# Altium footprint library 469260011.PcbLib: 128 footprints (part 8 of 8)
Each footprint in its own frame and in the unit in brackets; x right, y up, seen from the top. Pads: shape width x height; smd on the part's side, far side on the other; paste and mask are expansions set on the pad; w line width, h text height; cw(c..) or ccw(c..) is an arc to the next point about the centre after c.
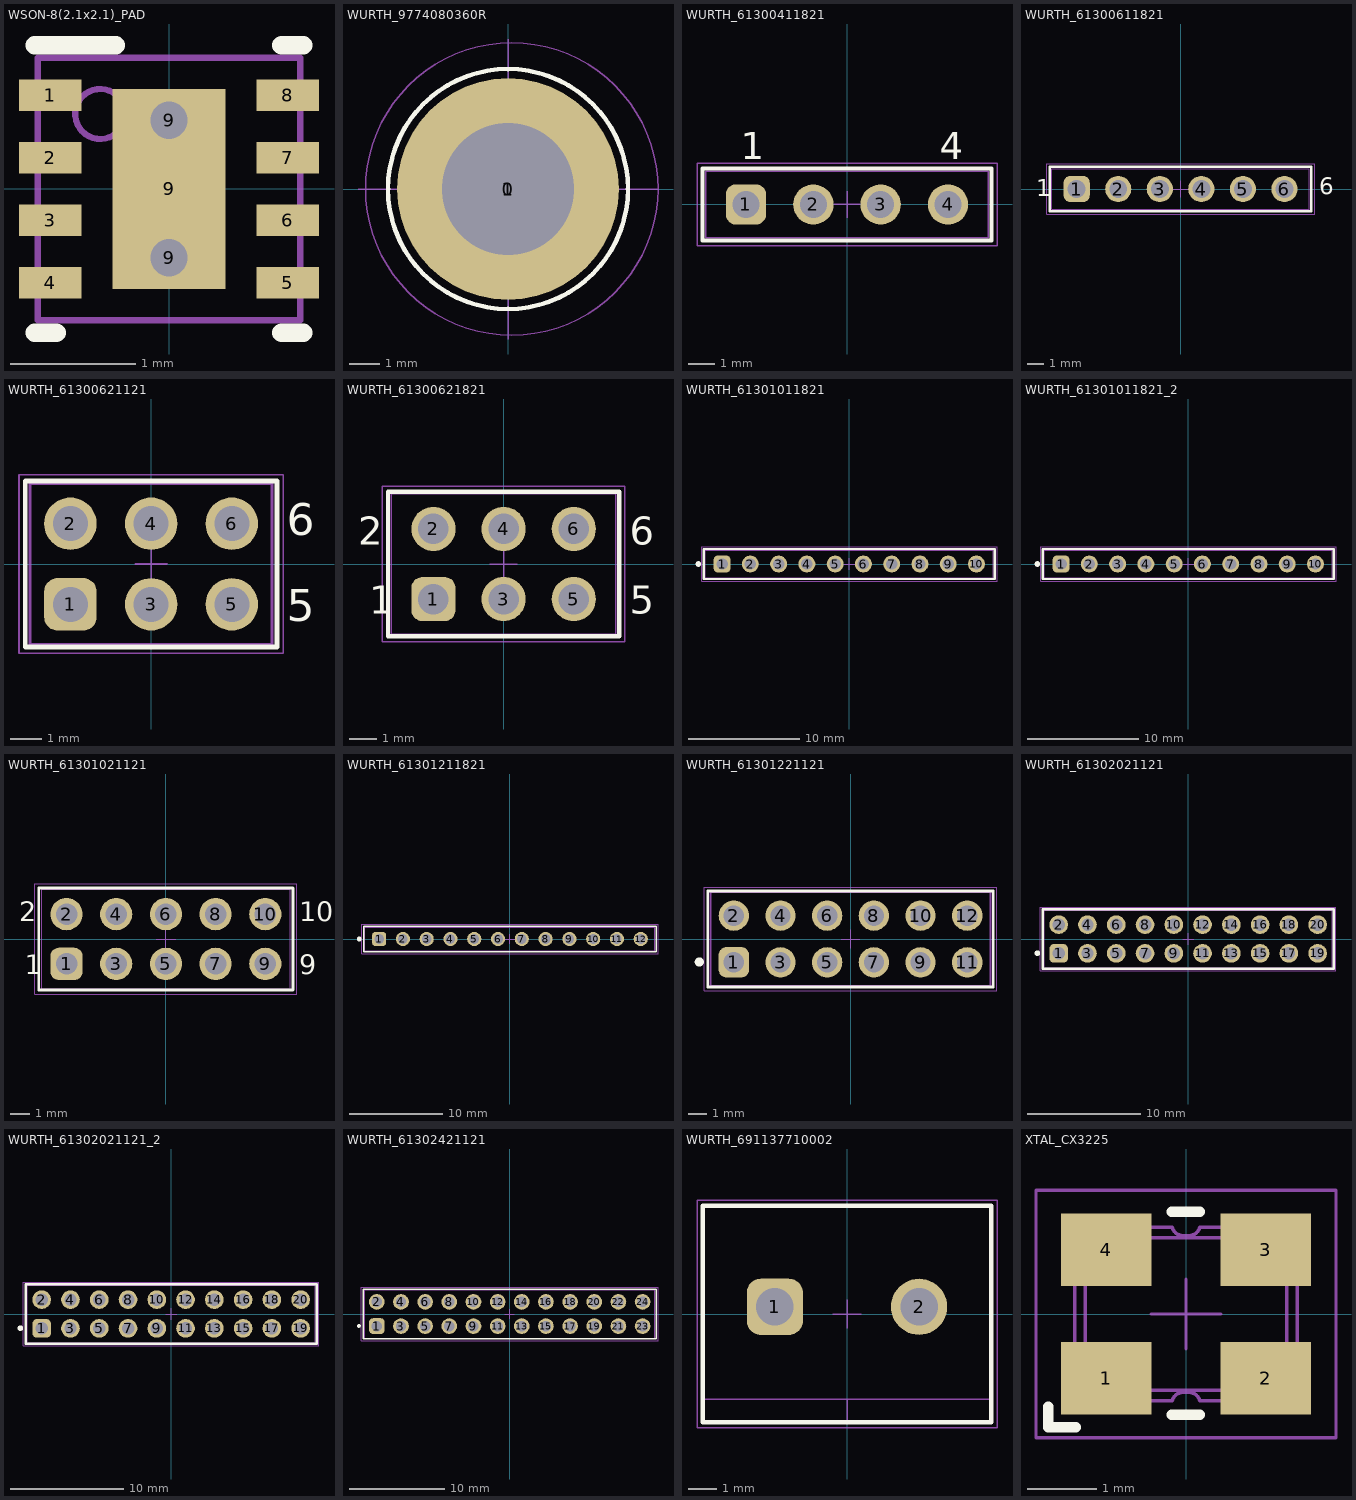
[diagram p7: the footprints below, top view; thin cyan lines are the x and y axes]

## WSON-8(2.1x2.1)_PAD [mm] "8-WFDFN Exposed Pad, 8-WSON (2x2), DSG0008A_TEX"
height 0.8
pads (11):
  rect 0.5x0.25 smd paste+0 mask+0: 1(-0.95,0.75) 2(-0.95,0.25) 3(-0.95,-0.25) 4(-0.95,-0.75) 5(0.95,-0.75) 6(0.95,-0.25) 7(0.95,0.25) 8(0.95,0.75)
  round 0.5 hole 0.3 paste+0 mask+0.076: 9(0,-0.55) 9(0,0.55)
  rect 0.9x1.6 smd paste-0.45 mask+0: 9(0,0)
Top Overlay:
  lines w0.15: -1.075,-1.15 -0.9,-1.15 ; -1.075,1.15 -0.425,1.15 ; 0.9,-1.15 1.075,-1.15 ; 0.9,1.15 1.075,1.15
Top Paste:
  region: -0.449,-0.761 -0.45,-0.751 -0.45,-0.149 -0.449,-0.139 -0.446,-0.13 -0.442,-0.122 -0.436,-0.114 -0.428,-0.108 -0.42,-0.104 -0.411,-0.101 -0.401,-0.1 0.401,-0.1 0.411,-0.101 0.42,-0.104 0.428,-0.108 0.436,-0.114 0.442,-0.122 0.446,-0.13 0.449,-0.139 0.45,-0.149 0.45,-0.751 0.449,-0.761 0.446,-0.77 0.442,-0.778 0.436,-0.786 0.428,-0.792 0.42,-0.796 0.411,-0.799 0.401,-0.8 -0.401,-0.8 -0.411,-0.799 -0.42,-0.796 -0.428,-0.792 -0.436,-0.786 -0.442,-0.778 -0.446,-0.77
  region: -0.449,0.139 -0.45,0.149 -0.45,0.751 -0.449,0.761 -0.446,0.77 -0.442,0.778 -0.436,0.786 -0.428,0.792 -0.42,0.796 -0.411,0.799 -0.401,0.8 0.401,0.8 0.411,0.799 0.42,0.796 0.428,0.792 0.436,0.786 0.442,0.778 0.446,0.77 0.449,0.761 0.45,0.751 0.45,0.149 0.449,0.139 0.446,0.13 0.442,0.122 0.436,0.114 0.428,0.108 0.42,0.104 0.411,0.101 0.401,0.1 -0.401,0.1 -0.411,0.101 -0.42,0.104 -0.428,0.108 -0.436,0.114 -0.442,0.122 -0.446,0.13
Top Assembly:
  circle w0.05: c-0.55,0.6 r0.2
  lines w0.05: -1.05,-1.05 1.05,-1.05 1.05,1.05 -1.05,1.05 -1.05,-1.05
3D body "DSG0008A.stp": height 0.77, standoff 0, extent -1,-1 1,1

## WURTH_9774080360R [mm]
pads (2):
  round 2.2 hole 4.4 unplated: 0(0,0)
  round 7.4 smd paste-10: 1(0,0)
Top Overlay:
  circle w0.15: c0,0 r4
Top Paste:
  lines w1.4: -2.767,-1.083 ccw(c0,0) -1.202,-2.718 ; -2.718,1.202 cw(c0,0) -1.083,2.767 ; 1.083,-2.767 ccw(c0,0) 2.718,-1.202 ; 1.202,2.718 cw(c0,0) 2.767,1.083
Mechanical 1:
  lines w0.05: -5,0 5,0 ; 0,-5 0,5
Top Assembly:
  circle w0.05: c0,0 r4
  text ".Designator" at -2.252,-0.226 h1
Top Courtyard:
  circle w0.05: c0.125,0 r4.875
  lines w0.05: -0.5,0 0.5,0 ; 0,-0.5 0,0.5
3D body "Download_STP_9774080360R_rev1.stp": height 9.4, standoff 0, extent -2.918,-2.934 3.076,3.053

## WURTH_61300411821 [mm] "Socket Header, Pitch 2.54 mm, THT, Vertical, single row, 4p"
height 8.5
pads (4):
  rrect50% 1.52x1.52 hole 1.02: 1(-3.81,0)
  round 1.52 hole 1.02: 2(-1.27,0) 3(1.27,0) 4(3.81,0)
Top Overlay:
  lines w0.15: -5.455,-1.35 -5.455,1.35 5.455,1.35 5.455,-1.35 -5.455,-1.35
  text "1" at -4,1.7 h1.02
  text "4" at 3.5,1.7 h1.02
Top Assembly:
  lines w0.05: -5.33,-1.25 5.33,-1.25 5.33,1.25 -5.33,1.25 -5.33,-1.25
  text ".Designator" at -2.252,-0.226 h1
Top Courtyard:
  lines w0.05: -0.5,0 0.5,0 ; 0,-0.5 0,0.5 ; -5.655,-1.55 -5.655,1.55 5.655,1.55 5.655,-1.55 -5.655,-1.55
3D body "61300411821.stp": height 8.55, standoff -3.05, extent -5.33,-1.25 5.33,1.25

## WURTH_61300611821 [mm] "Socket Header, Pitch 2.54 mm, THT, Vertical, single row, 6p"
height 8.5
pads (6):
  rrect50% 1.6x1.6 hole 1.1: 1(-6.35,0)
  round 1.6 hole 1.1: 2(-3.81,0) 3(-1.27,0) 4(1.27,0) 5(3.81,0) 6(6.35,0)
Top Overlay:
  lines w0.15: -7.995,-1.35 -7.995,1.35 7.995,1.35 7.995,-1.35 -7.995,-1.35
  text "1" at -8.84,-0.45 h1.02
  text "6" at 8.49,-0.35 h1.02
Top Assembly:
  lines w0.05: -7.87,-1.25 7.87,-1.25 7.87,1.25 -7.87,1.25 -7.87,-1.25
  text ".Designator" at -2.252,-0.226 h1
Top Courtyard:
  lines w0.05: -0.5,0 0.5,0 ; 0,-0.5 0,0.5 ; -8.195,-1.55 -8.195,1.55 8.195,1.55 8.195,-1.55 -8.195,-1.55
3D body "61300611821.stp": height 8.55, standoff -3.06, extent -7.87,-1.25 7.87,1.25

## WURTH_61300621121 [mm] "Pin Header, pitch 2.54 mm, THT, Vertical, dual row, 6p"
height 8.54
pads (6):
  rrect50% 1.65x1.65 hole 1.1: 1(-2.54,-1.27)
  round 1.65 hole 1.1: 2(-2.54,1.27) 3(0,-1.27) 4(0,1.27) 5(2.54,-1.27) 6(2.54,1.27)
Top Overlay:
  lines w0.15: -3.96,-2.615 3.96,-2.615 3.96,2.615 -3.96,2.615 -3.96,-2.615
  text "5" at 4.27,-1.8 h1.02
  text "6" at 4.27,0.9 h1.02
Top Assembly:
  lines w0.1: -3.81,-2.54 3.81,-2.54 3.81,2.54 -3.81,2.54 -3.81,-2.54
  text ".Designator" at -2.252,-0.226 h1
Top Courtyard:
  lines w0.05: -0.5,0 0.5,0 ; 0,-0.5 0,0.5 ; -4.16,-2.815 -4.16,2.815 4.16,2.815 4.16,-2.815 -4.16,-2.815
3D body "61300621121.stp": height 8.59, standoff -2.95, extent -3.81,-2.54 3.81,2.54

## WURTH_61300621821 [mm] "Socket Header, Pitch 2.54 mm, THT, Vertical, dual row, 6p"
height 8.4
pads (6):
  rrect50% 1.6x1.6 hole 1.1: 1(-2.54,-1.27)
  round 1.6 hole 1.1: 2(-2.54,1.27) 3(0,-1.27) 4(0,1.27) 5(2.54,-1.27) 6(2.54,1.27)
Top Overlay:
  lines w0.15: -4.185,-2.615 -4.185,2.615 4.185,2.615 4.185,-2.615 -4.185,-2.615
  text "5" at 4.57,-1.8 h1.02
  text "6" at 4.57,0.7 h1.02
  text "2" at -5.27,0.7 h1.02
  text "1" at -4.87,-1.8 h1.02
Top Assembly:
  lines w0.05: -4.06,-2.54 4.06,-2.54 4.06,2.54 -4.06,2.54 -4.06,-2.54
  text ".Designator" at -2.252,-0.226 h1
Top Courtyard:
  lines w0.05: -0.5,0 0.5,0 ; 0,-0.5 0,0.5 ; -4.385,-2.815 4.385,-2.815 4.385,2.815 -4.385,2.815 -4.385,-2.815
3D body "61300621821.stp": height 8.45, standoff -3.05, extent -4.06,-2.54 4.06,2.54

## WURTH_61301011821 [mm] "Socket Header, Pitch 2.54 mm, THT, Vertical, single row, 10p"
height 8.5
pads (10):
  rrect50% 1.52x1.52 hole 1.02: 1(-11.43,0)
  round 1.52 hole 1.02: 2(-8.89,0) 3(-6.35,0) 4(-3.81,0) 5(-1.27,0) 6(1.27,0) 7(3.81,0) 8(6.35,0) 9(8.89,0) 10(11.43,0)
Top Overlay:
  circle w0.25: c-13.56,0 r0.125
  lines w0.2: -13.075,-1.35 13.075,-1.35 13.075,1.35 -13.075,1.35 -13.075,-1.35
Top Assembly:
  lines w0.1: -12.95,-1.25 12.95,-1.25 12.95,1.25 -12.95,1.25 -12.95,-1.25
  text ".Designator" at -2.252,-0.226 h1
Top Courtyard:
  lines w0.05: -0.5,0 0.5,0 ; 0,-0.5 0,0.5 ; -13.275,-1.55 13.275,-1.55 13.275,1.55 -13.275,1.55 -13.275,-1.55
3D body "61301011821.stp": height 8.55, standoff -3.06, extent -12.95,-1.25 12.95,1.25

## WURTH_61301011821_2 [mm]
pads (10):
  rrect50% 1.52x1.52 hole 1.02: 1(-11.43,0)
  round 1.52 hole 1.02: 2(-8.89,0) 3(-6.35,0) 4(-3.81,0) 5(-1.27,0) 6(1.27,0) 7(3.81,0) 8(6.35,0) 9(8.89,0) 10(11.43,0)
Top Overlay:
  circle w0.25: c-13.56,0 r0.125
  lines w0.2: -13.075,-1.35 -13.075,1.35 13.075,1.35 13.075,-1.35 -13.075,-1.35
Top Assembly:
  lines w0.1: -12.95,-1.25 -12.95,1.25 12.95,1.25 12.95,-1.25 -12.95,-1.25
  text ".Designator" at -2.252,-0.226 h1
Top Courtyard:
  lines w0.05: -0.5,0 0.5,0 ; 0,-0.5 0,0.5 ; -13.275,-1.55 -13.275,1.55 13.275,1.55 13.275,-1.55 -13.275,-1.55
3D body "61301011821.stp": height 8.55, standoff -3.06, extent -12.95,-1.25 12.95,1.25

## WURTH_61301021121 [mm] "Pin Header, pitch 2.54 mm, THT, Vertical, dual row, 10p"
height 8.54
pads (10):
  rrect50% 1.65x1.65 hole 1.1: 1(-5.08,-1.27)
  round 1.65 hole 1.1: 2(-5.08,1.27) 3(-2.54,-1.27) 4(-2.54,1.27) 5(0,-1.27) 6(0,1.27) 7(2.54,-1.27) 8(2.54,1.27) 9(5.08,-1.27) 10(5.08,1.27)
Top Overlay:
  lines w0.15: -6.5,-2.615 -6.5,2.615 6.5,2.615 6.5,-2.615 -6.5,-2.615
  text "10" at 6.81,0.9 h1.02
  text "9" at 6.81,-1.8 h1.02
  text "1" at -7.21,-1.8 h1.02
  text "2" at -7.51,0.9 h1.02
Top Assembly:
  lines w0.05: -6.35,-2.54 -6.35,2.54 6.35,2.54 6.35,-2.54 -6.35,-2.54
  text ".Designator" at -2.252,-0.226 h1
Top Courtyard:
  lines w0.05: -0.5,0 0.5,0 ; 0,-0.5 0,0.5 ; -6.7,-2.815 6.7,-2.815 6.7,2.815 -6.7,2.815 -6.7,-2.815
3D body "61301021121.stp": height 8.59, standoff -2.95, extent -6.35,-2.54 6.35,2.54

## WURTH_61301211821 [mm] "Socket Header, Pitch 2.54 mm, THT, Vertical, single row, 12p"
height 8.5
pads (12):
  rrect50% 1.52x1.52 hole 1.02: 1(-13.97,0)
  round 1.52 hole 1.02: 2(-11.43,0) 3(-8.89,0) 4(-6.35,0) 5(-3.81,0) 6(-1.27,0) 7(1.27,0) 8(3.81,0) 9(6.35,0) 10(8.89,0) 11(11.43,0) 12(13.97,0)
Top Overlay:
  circle w0.25: c-16.1,0 r0.125
  lines w0.15: -15.615,-1.35 -15.615,1.35 15.615,1.35 15.615,-1.35 -15.615,-1.35
Top Assembly:
  lines w0.05: -15.49,-1.25 -15.49,1.25 15.49,1.25 15.49,-1.25 -15.49,-1.25
  text ".Designator" at -2.252,-0.226 h1
Top Courtyard:
  lines w0.05: -0.5,0 0.5,0 ; 0,-0.5 0,0.5 ; -15.815,-1.55 -15.815,1.55 15.815,1.55 15.815,-1.55 -15.815,-1.55
3D body "61301211821.stp": height 8.55, standoff -3.06, extent -15.49,-1.25 15.49,1.25

## WURTH_61301221121 [mm] "Pin Header, pitch 2.54 mm, THT, Vertical, dual row, 12p"
height 8.54
pads (12):
  rrect50% 1.65x1.65 hole 1.1: 1(-6.35,-1.27)
  round 1.65 hole 1.1: 2(-6.35,1.27) 3(-3.81,-1.27) 4(-3.81,1.27) 5(-1.27,-1.27) 6(-1.27,1.27) 7(1.27,-1.27) 8(1.27,1.27) 9(3.81,-1.27) 10(3.81,1.27) 11(6.35,-1.27) 12(6.35,1.27)
Top Overlay:
  circle w0.25: c-8.23,-1.25 r0.125
  lines w0.15: -7.77,-2.615 7.77,-2.615 7.77,2.615 -7.77,2.615 -7.77,-2.615
Top Assembly:
  lines w0.1: -7.62,-2.54 7.62,-2.54 7.62,2.54 -7.62,2.54 -7.62,-2.54
  text ".Designator" at -3.378,-0.339 h1.5
Top Courtyard:
  lines w0.05: -0.5,0 0.5,0 ; 0,-0.5 0,0.5 ; -7.97,-2.815 -7.97,2.815 7.97,2.815 7.97,-2.815 -7.97,-2.815
3D body "61301221121.stp": height 8.59, standoff -2.95, extent -7.62,-2.54 7.62,2.54

## WURTH_61302021121 [mm] "Pin Header, pitch 2.54 mm, THT, Vertical, dual row, 20p"
height 8.54
pads (20):
  rrect50% 1.65x1.65 hole 1.1: 1(-11.43,-1.27)
  round 1.65 hole 1.1: 2(-11.43,1.27) 3(-8.89,-1.27) 4(-8.89,1.27) 5(-6.35,-1.27) 6(-6.35,1.27) 7(-3.81,-1.27) 8(-3.81,1.27) 9(-1.27,-1.27) 10(-1.27,1.27) 11(1.27,-1.27) 12(1.27,1.27) 13(3.81,-1.27) 14(3.81,1.27) 15(6.35,-1.27) 16(6.35,1.27) 17(8.89,-1.27) 18(8.89,1.27) 19(11.43,-1.27) 20(11.43,1.27)
Top Overlay:
  circle w0.25: c-13.31,-1.25 r0.125
  lines w0.2: -12.85,-2.615 12.85,-2.615 12.85,2.615 -12.85,2.615 -12.85,-2.615
Top Assembly:
  circle w0.05: c-11.43,-1.27 r0.5
  lines w0.1: -12.7,-2.54 12.7,-2.54 12.7,2.54 -12.7,2.54 -12.7,-2.54
  text ".Designator" at -2.252,-0.226 h1
Top Courtyard:
  lines w0.05: -0.5,0 0.5,0 ; 0,-0.5 0,0.5 ; -13.05,-2.815 13.05,-2.815 13.05,2.815 -13.05,2.815 -13.05,-2.815
3D body "61302021121.stp": height 8.59, standoff -2.95, extent -12.7,-2.54 12.7,2.54

## WURTH_61302021121_2 [mm]
pads (20):
  rrect50% 1.65x1.65 hole 1.1: 1(-11.43,-1.27)
  round 1.65 hole 1.1: 2(-11.43,1.27) 3(-8.89,-1.27) 4(-8.89,1.27) 5(-6.35,-1.27) 6(-6.35,1.27) 7(-3.81,-1.27) 8(-3.81,1.27) 9(-1.27,-1.27) 10(-1.27,1.27) 11(1.27,-1.27) 12(1.27,1.27) 13(3.81,-1.27) 14(3.81,1.27) 15(6.35,-1.27) 16(6.35,1.27) 17(8.89,-1.27) 18(8.89,1.27) 19(11.43,-1.27) 20(11.43,1.27)
Top Overlay:
  circle w0.25: c-13.31,-1.25 r0.125
  lines w0.2: -12.85,-2.615 -12.85,2.615 12.85,2.615 12.85,-2.615 -12.85,-2.615
Top Assembly:
  circle w0.05: c-11.43,-1.27 r0.5
  lines w0.1: -12.7,-2.54 12.7,-2.54 12.7,2.54 -12.7,2.54 -12.7,-2.54
  text ".Designator" at -2.252,-0.226 h1
Top Courtyard:
  lines w0.05: -0.5,0 0.5,0 ; 0,-0.5 0,0.5 ; -13.05,-2.815 13.05,-2.815 13.05,2.815 -13.05,2.815 -13.05,-2.815
3D body "61302021121.stp": height 8.59, standoff -2.95, extent -12.7,-2.54 12.7,2.54

## WURTH_61302421121 [mm] "Pin Header, pitch 2.54 mm, THT, Vertical, dual row, 24p"
height 8.54
pads (24):
  rrect50% 1.65x1.65 hole 1.1: 1(-13.97,-1.27)
  round 1.65 hole 1.1: 2(-13.97,1.27) 3(-11.43,-1.27) 4(-11.43,1.27) 5(-8.89,-1.27) 6(-8.89,1.27) 7(-6.35,-1.27) 8(-6.35,1.27) 9(-3.81,-1.27) 10(-3.81,1.27) 11(-1.27,-1.27) 12(-1.27,1.27) 13(1.27,-1.27) 14(1.27,1.27) 15(3.81,-1.27) 16(3.81,1.27) 17(6.35,-1.27) 18(6.35,1.27) 19(8.89,-1.27) 20(8.89,1.27) 21(11.43,-1.27) 22(11.43,1.27) 23(13.97,-1.27) 24(13.97,1.27)
Top Overlay:
  circle w0.2: c-15.85,-1.25 r0.1
  lines w0.15: -15.39,-2.615 15.39,-2.615 15.39,2.615 -15.39,2.615 -15.39,-2.615
Top Assembly:
  lines w0.1: -15.24,-2.54 -15.24,2.54 15.24,2.54 15.24,-2.54 -15.24,-2.54
  text ".Designator" at -2.252,-0.226 h1
Top Courtyard:
  lines w0.05: -0.5,0 0.5,0 ; 0,-0.5 0,0.5 ; -15.59,-2.815 -15.59,2.815 15.59,2.815 15.59,-2.815 -15.59,-2.815
3D body "61302421121.stp": height 8.59, standoff -2.95, extent -15.24,-2.54 15.24,2.54

## WURTH_691137710002 [mm] "Horizontal Cable Entry with Pressure Clamp, pitch 5mm, 02p"
height 11.5
pads (2):
  rrect50% 1.95x1.95 hole 1.3: 1(-2.5,0.25)
  round 1.95 hole 1.3: 2(2.5,0.25)
Top Overlay:
  lines w0.15: -5,-3.75 -5,3.75 5,3.75 5,-3.75 -5,-3.75
Top Assembly:
  lines w0.05: -5,-2.95 5,-2.95 ; 0,-3.75 0,-2.95 ; -5,-3.75 5,-3.75 5,3.75 -5,3.75 -5,-3.75
  text ".Designator" at -2.252,-0.226 h1
Top Courtyard:
  lines w0.05: -0.5,0 0.5,0 ; 0,-0.5 0,0.5 ; -5.2,-3.95 -5.2,3.95 5.2,3.95 5.2,-3.95 -5.2,-3.95
3D body "691137710002.stp": height 11.6, standoff -3.5, extent -5,-3.75 5,3.75

## XTAL_CX3225 [mm] "KYOCERA"
height 0.6
pads (4):
  rect 1.3x1.05 smd mask+0.08: 1(-1.15,-0.925) 2(1.15,-0.925) 3(1.15,0.925) 4(-1.15,0.925)
Top Overlay:
  lines w0.15: -1.983,-1.331 -1.983,-1.631 -1.583,-1.631 ; -0.203,-1.448 0.197,-1.448 ; -0.203,1.473 0.197,1.473
Top Assembly:
  circle w0.05: c-1.15,-0.8 r0.15
  lines w0.05: -1.6,-1.05 cw(c-1.6,-1.25) -1.4,-1.25 -0.197,-1.25 cw(c-0.05,-1.28) -0.05,-1.13 0.05,-1.13 cw(c0.05,-1.28) 0.197,-1.25 1.4,-1.25 cw(c1.6,-1.25) 1.6,-1.05 1.6,1.05 cw(c1.6,1.25) 1.4,1.25 0.197,1.25 cw(c0.05,1.28) 0.05,1.13 -0.05,1.13 cw(c-0.05,1.28) -0.197,1.25 -1.4,1.25 cw(c-1.6,1.25) -1.6,1.05 -1.6,-1.05 ; -1.45,-0.8 ccw(c-1.15,-0.8) -1.15,-1.1 1.15,-1.1 ccw(c1.15,-0.8) 1.45,-0.8 1.45,0.8 ccw(c1.15,0.8) 1.15,1.1 -1.15,1.1 ccw(c-1.15,0.8) -1.45,0.8 -1.45,-0.8
  text ".Designator" at -2.252,-0.226 h1
Top Courtyard:
  lines w0.05: -0.5,0 0.5,0 ; 0,-0.5 0,0.5 ; -2.159,-1.778 -2.159,1.778 2.159,1.778 2.159,-1.778 -2.159,-1.778
3D body "User Library-SMD-3225_4P.step": height 1.05, standoff 0, extent -1.6,-1.25 1.6,1.25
